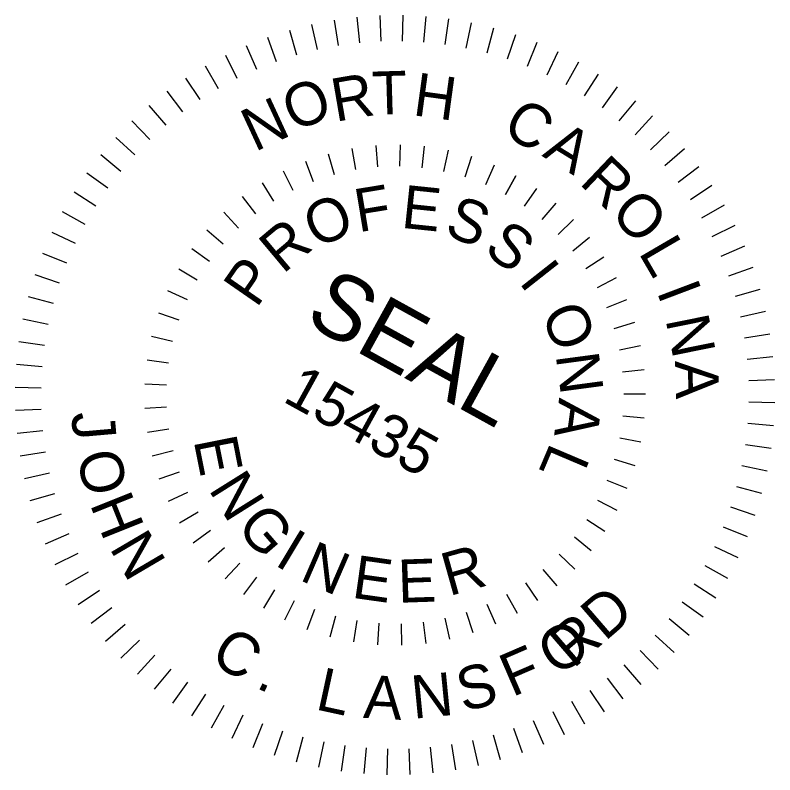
# Model space of a CAD drawing. Extents: x 1519210 to 1521378, y 637447 to 639183.
# Drawn here: x 1521204.6 to 1521288.4, y 638245.8 to 638329.6 of the extents above; entities that cross this region are included whole.
import ezdxf

# ---------------------------------------------------------------- set-up
doc = ezdxf.new("R2010")
doc.units = 0
doc.layers.add('Old_Level_21', color=7, linetype='Continuous')

msp = doc.modelspace()

# ---------------------------------------------------------------- linework, layer by layer
at = {"layer": 'Old_Level_21'}
for p, q in [((1521244.838, 638329.619), (1521244.956, 638326.764)), ((1521247.373, 638329.644), (1521247.314, 638326.786)), ((1521239.807, 638329.11), (1521240.262, 638326.292)), ((1521242.314, 638329.44), (1521242.601, 638326.599)), ((1521249.901, 638329.511), (1521249.668, 638326.667)), ((1521252.419, 638329.236), (1521252.017, 638326.404)), ((1521254.911, 638328.806), (1521254.336, 638326.002)), ((1521234.866, 638327.998), (1521235.66, 638325.256)), ((1521237.317, 638328.629), (1521237.945, 638325.843)), ((1521257.379, 638328.22), (1521256.634, 638325.463)), ((1521232.458, 638327.223), (1521233.414, 638324.532)), ((1521259.801, 638327.492), (1521258.895, 638324.783)), ((1521230.096, 638326.301), (1521231.216, 638323.675)), ((1521262.175, 638326.615), (1521261.107, 638323.968)), ((1521264.494, 638325.599), (1521263.267, 638323.02)), ((1521227.8, 638325.241), (1521229.074, 638322.686)), ((1521225.57, 638324.044), (1521226.995, 638321.567)), ((1521266.749, 638324.444), (1521265.369, 638321.942)), ((1521268.929, 638323.155), (1521267.403, 638320.74)), ((1521223.413, 638322.712), (1521224.99, 638320.326)), ((1521221.347, 638321.249), (1521223.062, 638318.969)), ((1521271.026, 638321.736), (1521269.358, 638319.42)), ((1521219.366, 638319.672), (1521221.217, 638317.493)), ((1521273.035, 638320.198), (1521271.229, 638317.985)), ((1521217.488, 638317.978), (1521219.471, 638315.914)), ((1521274.944, 638318.538), (1521273.011, 638316.436)), ((1521276.757, 638316.764), (1521274.693, 638314.781)), ((1521215.714, 638316.165), (1521217.816, 638314.232)), ((1521247.08, 638315.356), (1521247.029, 638312.977)), ((1521241.761, 638314.951), (1521242.172, 638312.602)), ((1521244.411, 638315.283), (1521244.59, 638312.906)), ((1521249.743, 638315.175), (1521249.464, 638312.808)), ((1521252.378, 638314.734), (1521251.87, 638312.405)), ((1521278.451, 638314.887), (1521276.272, 638313.035)), ((1521214.055, 638314.255), (1521216.267, 638312.45)), ((1521239.159, 638314.363), (1521239.794, 638312.066)), ((1521254.955, 638314.041), (1521254.225, 638311.774)), ((1521236.624, 638313.53), (1521237.475, 638311.308)), ((1521257.451, 638313.103), (1521256.51, 638310.919)), ((1521280.028, 638312.905), (1521277.748, 638311.19)), ((1521212.516, 638312.246), (1521214.832, 638310.579)), ((1521234.179, 638312.457), (1521235.24, 638310.323)), ((1521259.85, 638311.929), (1521258.702, 638309.846)), ((1521258.702, 638309.846), (1521259.85, 638311.929)), ((1521231.855, 638311.15), (1521233.113, 638309.129)), ((1521262.124, 638310.528), (1521260.78, 638308.566)), ((1521281.491, 638310.839), (1521279.105, 638309.262)), ((1521211.098, 638310.15), (1521213.512, 638308.624)), ((1521229.659, 638309.624), (1521231.113, 638307.738)), ((1521264.25, 638308.918), (1521262.723, 638307.09)), ((1521282.823, 638308.682), (1521280.346, 638307.257)), ((1521209.808, 638307.969), (1521212.31, 638306.59)), ((1521227.627, 638307.894), (1521229.259, 638306.158)), ((1521266.211, 638307.109), (1521264.514, 638305.436)), ((1521284.02, 638306.452), (1521281.465, 638305.178)), ((1521208.653, 638305.715), (1521211.232, 638304.488)), ((1521225.77, 638305.979), (1521227.558, 638304.406)), ((1521267.991, 638305.117), (1521266.14, 638303.617)), ((1521224.106, 638303.89), (1521226.037, 638302.502)), ((1521285.08, 638304.157), (1521282.454, 638303.036)), ((1521207.638, 638303.396), (1521210.284, 638302.328)), ((1521269.566, 638302.961), (1521267.583, 638301.649)), ((1521222.65, 638301.653), (1521224.705, 638300.453)), ((1521286.002, 638301.794), (1521283.311, 638300.838)), ((1521206.761, 638301.022), (1521209.469, 638300.116)), ((1521270.93, 638300.666), (1521268.824, 638299.549)), ((1521206.032, 638298.599), (1521208.789, 638297.855)), ((1521221.419, 638299.285), (1521223.58, 638298.289)), ((1521286.777, 638299.386), (1521284.035, 638298.592)), ((1521272.064, 638298.248), (1521269.859, 638297.341)), ((1521287.408, 638296.935), (1521284.622, 638296.307)), ((1521205.447, 638296.132), (1521208.25, 638295.557)), ((1521220.424, 638296.807), (1521222.67, 638296.027)), ((1521272.957, 638295.734), (1521270.676, 638295.044)), ((1521287.89, 638294.446), (1521285.071, 638293.991)), ((1521205.017, 638293.639), (1521207.848, 638293.238)), ((1521219.666, 638294.246), (1521221.979, 638293.685)), ((1521273.606, 638293.146), (1521271.273, 638292.679)), ((1521288.22, 638291.938), (1521285.379, 638291.651)), ((1521204.741, 638291.122), (1521207.585, 638290.889)), ((1521219.165, 638291.624), (1521221.521, 638291.289)), ((1521274.004, 638290.506), (1521271.633, 638290.263)), ((1521288.398, 638289.414), (1521285.543, 638289.296)), ((1521204.608, 638288.594), (1521207.467, 638288.535)), ((1521218.921, 638288.968), (1521221.297, 638288.864)), ((1521274.14, 638287.843), (1521271.76, 638287.828)), ((1521288.423, 638286.879), (1521285.565, 638286.938)), ((1521204.633, 638286.06), (1521207.488, 638286.177)), ((1521218.927, 638286.302), (1521221.304, 638286.421)), ((1521274.023, 638285.172), (1521271.651, 638285.394)), ((1521288.29, 638284.351), (1521285.446, 638284.584)), ((1521204.812, 638283.535), (1521207.653, 638283.822)), ((1521219.193, 638283.642), (1521221.55, 638283.994)), ((1521273.644, 638282.529), (1521271.306, 638282.982)), ((1521288.015, 638281.834), (1521285.183, 638282.235)), ((1521205.142, 638281.027), (1521207.96, 638281.482)), ((1521219.719, 638281.026), (1521222.025, 638281.602)), ((1521273.018, 638279.936), (1521270.733, 638280.609)), ((1521287.585, 638279.341), (1521284.781, 638279.916)), ((1521205.623, 638278.538), (1521208.409, 638279.166)), ((1521220.489, 638278.472), (1521222.735, 638279.27)), ((1521272.14, 638277.414), (1521269.935, 638278.306)), ((1521206.254, 638276.088), (1521208.996, 638276.881)), ((1521221.507, 638276.004), (1521223.661, 638277.014)), ((1521286.999, 638276.873), (1521284.242, 638277.618)), ((1521271.025, 638274.989), (1521268.913, 638276.086)), ((1521286.271, 638274.451), (1521283.562, 638275.357)), ((1521207.029, 638273.678), (1521209.72, 638274.635)), ((1521222.755, 638273.645), (1521224.806, 638274.859)), ((1521269.68, 638272.684), (1521267.685, 638273.979)), ((1521224.229, 638271.416), (1521226.151, 638272.824)), ((1521285.394, 638272.077), (1521282.747, 638273.144)), ((1521207.952, 638271.317), (1521210.577, 638272.437)), ((1521266.308, 638272.069), (1521268.175, 638270.588)), ((1521225.908, 638269.339), (1521227.686, 638270.926)), ((1521284.379, 638269.758), (1521281.799, 638270.985)), ((1521209.011, 638269.021), (1521211.567, 638270.295)), ((1521266.356, 638268.511), (1521264.647, 638270.167)), ((1521229.382, 638269.197), (1521227.763, 638267.447)), ((1521264.407, 638266.687), (1521262.866, 638268.5)), ((1521283.223, 638267.504), (1521280.721, 638268.883)), ((1521210.208, 638266.791), (1521212.685, 638268.216)), ((1521229.826, 638265.723), (1521231.263, 638267.621)), ((1521262.292, 638265.063), (1521260.936, 638267.016)), ((1521281.934, 638265.323), (1521279.52, 638266.849)), ((1521211.54, 638264.634), (1521213.926, 638266.211)), ((1521232.027, 638264.214), (1521233.273, 638266.243)), ((1521234.363, 638262.926), (1521235.414, 638265.063)), ((1521260.034, 638263.645), (1521258.865, 638265.718)), ((1521213.003, 638262.568), (1521215.283, 638264.283)), ((1521257.643, 638262.448), (1521256.682, 638264.63)), ((1521280.516, 638263.227), (1521278.199, 638264.894)), ((1521236.815, 638261.871), (1521237.652, 638264.099)), ((1521255.15, 638261.497), (1521254.406, 638263.754)), ((1521239.358, 638261.056), (1521239.974, 638263.358)), ((1521241.964, 638260.489), (1521242.357, 638262.84)), ((1521244.617, 638260.179), (1521244.782, 638262.555)), ((1521249.949, 638260.327), (1521249.653, 638262.687)), ((1521252.58, 638260.784), (1521252.055, 638263.108)), ((1521278.977, 638261.217), (1521276.764, 638263.023)), ((1521214.58, 638260.586), (1521216.76, 638262.438)), ((1521247.288, 638260.122), (1521247.22, 638262.505)), ((1521277.318, 638259.308), (1521275.216, 638261.241)), ((1521216.274, 638258.709), (1521218.338, 638260.692)), ((1521275.543, 638257.495), (1521273.56, 638259.559)), ((1521218.087, 638256.935), (1521220.02, 638259.037)), ((1521273.666, 638255.801), (1521271.814, 638257.981)), ((1521219.997, 638255.276), (1521221.802, 638257.488)), ((1521222.006, 638253.737), (1521223.674, 638256.053)), ((1521271.684, 638254.224), (1521269.969, 638256.504)), ((1521269.618, 638252.761), (1521268.041, 638255.147)), ((1521224.102, 638252.318), (1521225.629, 638254.732)), ((1521226.283, 638251.029), (1521227.662, 638253.531)), ((1521267.462, 638251.429), (1521266.037, 638253.906)), ((1521265.231, 638250.232), (1521263.957, 638252.788)), ((1521228.537, 638249.874), (1521229.764, 638252.453)), ((1521262.935, 638249.173), (1521261.815, 638251.798)), ((1521230.856, 638248.859), (1521231.924, 638251.505)), ((1521260.574, 638248.25), (1521259.617, 638250.941)), ((1521233.23, 638247.982), (1521234.136, 638250.69)), ((1521235.653, 638247.253), (1521236.397, 638250.01)), ((1521258.165, 638247.475), (1521257.371, 638250.217)), ((1521238.12, 638246.668), (1521238.695, 638249.471)), ((1521253.225, 638246.363), (1521252.77, 638249.181)), ((1521255.714, 638246.844), (1521255.086, 638249.63)), ((1521240.613, 638246.238), (1521241.014, 638249.069)), ((1521243.13, 638245.962), (1521243.363, 638248.806)), ((1521245.658, 638245.829), (1521245.717, 638248.688)), ((1521248.193, 638245.854), (1521248.075, 638248.709)), ((1521250.717, 638246.033), (1521250.43, 638248.874))]:
    msp.add_line(p, q, dxfattribs=at)

# ---------------------------------------------------------------- texts
for s, height, rotation, p in [('R', 4.757, 9.79753, (1521239.939, 638317.869)), ('T', 4.757, 1.63656, (1521244.026, 638318.656)), ('H', 4.757, 352.20462, (1521248.381, 638318.622)), ('O', 4.757, 22.85426, (1521235.373, 638316.726)), ('N', 4.757, 24.81369, (1521231.04, 638314.525)), ('C', 4.757, 328.49393, (1521258.149, 638316.729)), ('A', 4.757, 328.49393, (1521262.657, 638314.136)), ('R', 4.757, 316.48462, (1521266.733, 638311.088)), ('F', 4.757, 9.37758, (1521242.475, 638305.681)), ('E', 4.757, 354.08133, (1521247.109, 638306.2)), ('O', 4.757, 24.67382, (1521237.852, 638303.848)), ('S', 4.757, 338.78509, (1521251.811, 638305.476)), ('O', 4.757, 313.42781, (1521270.109, 638307.663)), ('R', 4.757, 39.97007, (1521234.14, 638301.014)), ('S', 4.757, 323.48884, (1521256.163, 638303.528)), ('L', 4.757, 300.29152, (1521273.325, 638303.471)), ('P', 4.757, 55.26632, (1521231.233, 638297.232)), ('I', 4.757, 308.19259, (1521260.098, 638300.187)), ('SEAL', 7.1422, 331.13696, (1521236.343, 638295.79)), ('I', 4.757, 290.71605, (1521275.352, 638299.2)), ('O', 4.757, 292.89635, (1521262.563, 638296.712)), ('N', 4.757, 281.42159, (1521276.357, 638296.084)), ('N', 4.757, 277.6001, (1521264.235, 638292.151)), ('A', 4.757, 271.65406, (1521277.412, 638291.492)), ('15435', 4.7575, 331.13696, (1521233.99, 638287.092)), ('A', 4.757, 262.30386, (1521264.639, 638287.479)), ('J', 4.757, 275.07198, (1521210.787, 638285.736)), ('E', 4.757, 281.20705, (1521224.287, 638282.735)), ('L', 4.757, 247.00761, (1521263.714, 638282.611)), ('O', 4.757, 283.14379, (1521211.338, 638281.104)), ('N', 4.757, 302.06213, (1521225.872, 638277.332)), ('H', 4.757, 291.78654, (1521212.804, 638275.72)), ('G', 4.757, 310.82836, (1521228.874, 638273.13)), ('N', 4.757, 300.45913, (1521214.945, 638270.871)), ('I', 4.757, 328.92316, (1521233.101, 638269.061)), ('N', 4.757, 336.55282, (1521235.852, 638267.363)), ('R', 4.757, 15.70185, (1521252.469, 638265.523)), ('E', 4.757, 351.94489, (1521241.643, 638265.384)), ('E', 4.757, 1.93077, (1521246.898, 638264.806)), (' RD', 4.7575, 40.80939, (1521264.856, 638256.326)), ('C', 4.757, 327.22692, (1521225.926, 638258.461)), ('O ', 4.7575, 32.13663, (1521264.239, 638256.64)), ('F', 4.757, 23.34402, (1521259.448, 638254.37)), ('L', 4.757, 347.75358, (1521237.61, 638253.077)), ('S', 4.757, 14.46139, (1521254.031, 638252.745)), ('A', 4.757, 356.75614, (1521242.957, 638252.121)), ('N', 4.757, 5.57876, (1521248.537, 638252.004)), ('.', 4.757, 334.96926, (1521231.043, 638255.494))]:
    msp.add_text(s, height=height, rotation=rotation, dxfattribs=at).set_placement(p)

doc.saveas('drawing.dxf')
